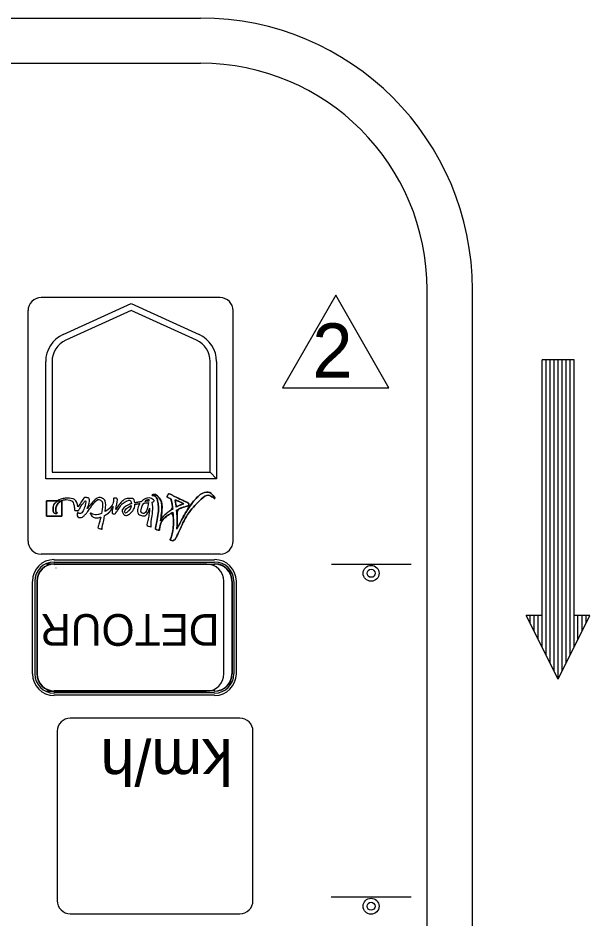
# Model space of a CAD drawing. Extents: x 1806 to 2022, y 110 to 389.
# Drawn here: x 1952.45 to 1967.73, y 255.29 to 279.36 of the extents above; entities that cross this region are included whole.
import ezdxf

# ---------------------------------------------------------------- set-up
doc = ezdxf.new("R2010")
doc.units = 0
for name, color, linetype in [('Level 10', 7, 'Continuous'), ('Level 2', 7, 'Continuous'), ('Level 44', 7, 'Continuous'), ('Level 50', 7, 'Continuous'), ('Level 53', 7, 'Continuous'), ('Level 60', 7, 'Continuous')]:
    doc.layers.add(name, color=color, linetype=linetype)

msp = doc.modelspace()

# ---------------------------------------------------------------- linework, layer by layer
at = {"layer": 'Level 10'}
for p, q in [((1895.86, 279.357), (1957.331, 279.357)), ((1895.86, 278.148), (1957.331, 278.148)), ((1963.38, 232.973), (1963.38, 272.1)), ((1964.59, 233.074), (1964.59, 272.1))]:
    msp.add_line(p, q, dxfattribs=at)
for radius in [7.258, 6.048]:
    msp.add_arc((1957.332, 272.1), radius, 0, 90, dxfattribs=at)
at = {"layer": 'Level 2'}
for p, q in [((1957.854, 271.887), (1953.069, 271.887)), ((1952.722, 265.385), (1952.722, 271.54)), ((1953.661, 270.905), (1955.476, 271.73)), ((1955.476, 271.542), (1953.732, 270.749)), ((1955.476, 271.73), (1957.29, 270.905)), ((1957.219, 270.749), (1955.476, 271.542)), ((1958.201, 265.385), (1958.201, 271.54)), ((1953.193, 267.05), (1953.193, 270.178)), ((1953.364, 270.178), (1953.364, 267.222)), ((1957.587, 267.222), (1957.587, 270.178)), ((1957.758, 270.178), (1957.758, 267.05)), ((1953.364, 267.222), (1957.587, 267.222)), ((1957.758, 267.05), (1957.587, 267.222)), ((1957.587, 267.222), (1957.758, 267.05)), ((1957.758, 267.05), (1953.193, 267.05)), ((1957.854, 265.038), (1953.069, 265.038)), ((1957.854, 265.038), (1953.069, 265.038))]:
    msp.add_line(p, q, dxfattribs=at)
for centre, radius, start, end in [((1953.069, 271.54), 0.347, 90, 180), ((1957.854, 271.54), 0.347, 360, 90), ((1953.992, 270.178), 0.799, 114.4568, 180), ((1956.959, 270.178), 0.799, 360, 65.5432), ((1953.992, 270.178), 0.628, 114.4568, 180), ((1956.959, 270.178), 0.628, 360, 65.5432), ((1953.069, 265.385), 0.347, 180, 270), ((1957.854, 265.385), 0.347, 270, 360)]:
    msp.add_arc(centre, radius, start, end, dxfattribs=at)
at = {"layer": 'Level 44'}
for p, q in [((1957.496, 264.768), (1953.205, 264.768)), ((1953.414, 264.887), (1957.705, 264.887)), ((1953.414, 264.822), (1957.705, 264.822)), ((1953.418, 264.77), (1953.414, 264.768)), ((1953.414, 264.768), (1957.705, 264.768)), ((1953.414, 264.768), (1957.705, 264.768)), ((1953.424, 264.77), (1957.715, 264.77)), ((1955.339, 264.774), (1955.339, 264.774)), ((1955.339, 264.774), (1955.339, 264.774)), ((1955.349, 264.776), (1955.349, 264.776)), ((1955.571, 264.774), (1955.571, 264.774)), ((1962.956, 264.762), (1960.823, 264.762)), ((1953.442, 264.722), (1953.438, 264.72)), ((1953.471, 264.664), (1953.467, 264.662)), ((1952.843, 261.84), (1952.843, 264.305)), ((1952.908, 261.84), (1952.908, 264.305)), ((1952.962, 261.84), (1952.962, 264.305)), ((1952.962, 261.84), (1952.962, 264.305)), ((1952.964, 264.305), (1952.964, 261.84)), ((1952.972, 261.842), (1952.972, 264.307)), ((1957.948, 261.84), (1957.948, 264.305)), ((1958.161, 264.305), (1958.161, 261.84)), ((1958.161, 264.305), (1958.161, 261.84)), ((1958.171, 264.307), (1958.171, 261.842)), ((1958.215, 264.305), (1958.215, 261.84)), ((1958.28, 264.305), (1958.28, 261.84)), ((1953.201, 261.378), (1957.492, 261.378)), ((1957.705, 261.384), (1953.414, 261.384)), ((1957.705, 261.384), (1953.414, 261.384)), ((1957.705, 261.33), (1953.414, 261.33)), ((1957.705, 261.265), (1953.414, 261.265)), ((1957.715, 261.386), (1953.424, 261.386)), ((1958.379, 260.654), (1953.851, 260.654)), ((1953.501, 260.306), (1953.501, 260.305)), ((1953.501, 260.305), (1953.501, 255.775)), ((1958.729, 255.775), (1958.729, 260.305)), ((1962.954, 255.867), (1960.821, 255.867)), ((1953.851, 255.426), (1958.379, 255.426))]:
    msp.add_line(p, q, dxfattribs=at)
for centre, radius in [((1961.885, 264.523), 0.213), ((1961.885, 264.523), 0.107), ((1961.883, 255.629), 0.213), ((1961.883, 255.629), 0.107)]:
    msp.add_circle(centre, radius, dxfattribs=at)
for centre, radius, start, end in [((1953.418, 264.309), 0.581, 90, 180), ((1953.418, 264.309), 0.516, 90, 180), ((1953.418, 264.309), 0.462, 90, 180), ((1953.418, 264.309), 0.462, 90, 180), ((1953.42, 264.309), 0.462, 90, 180), ((1953.428, 264.311), 0.462, 90, 180), ((1957.492, 264.309), 0.462, 0, 90), ((1957.705, 264.309), 0.581, 0, 90), ((1957.705, 264.309), 0.516, 0, 90), ((1957.705, 264.309), 0.462, 0, 90), ((1957.705, 264.309), 0.462, 0, 90), ((1957.715, 264.311), 0.462, 0, 90), ((1953.418, 261.839), 0.581, 180, 270), ((1953.418, 261.839), 0.516, 180, 270), ((1953.418, 261.839), 0.462, 180, 270), ((1953.418, 261.839), 0.462, 180, 270), ((1953.42, 261.839), 0.462, 180, 270), ((1953.428, 261.841), 0.462, 180, 270), ((1957.492, 261.839), 0.462, 270, 0), ((1957.705, 261.839), 0.462, 270, 360), ((1957.705, 261.839), 0.581, 270, 360), ((1957.705, 261.839), 0.516, 270, 360), ((1957.705, 261.839), 0.462, 270, 360), ((1957.715, 261.841), 0.462, 270, 360), ((1953.851, 260.306), 0.349, 90, 180), ((1958.38, 260.306), 0.349, 0, 90), ((1953.851, 255.777), 0.349, 180, 270), ((1958.38, 255.777), 0.349, 270, 0)]:
    msp.add_arc(centre, radius, start, end, dxfattribs=at)
at = {"layer": 'Level 50'}
for p, q in [((1966.45, 263.397), (1966.45, 270.224)), ((1967.304, 270.224), (1966.45, 270.224)), ((1966.45, 262.544), (1966.45, 270.224)), ((1966.557, 262.331), (1966.557, 270.224)), ((1966.664, 262.117), (1966.664, 270.224)), ((1966.77, 261.904), (1966.77, 270.224)), ((1966.877, 261.691), (1966.877, 270.224)), ((1966.984, 261.904), (1966.984, 270.224)), ((1967.09, 262.117), (1967.09, 270.224)), ((1967.197, 262.331), (1967.197, 270.224)), ((1967.304, 263.397), (1967.304, 270.224)), ((1967.304, 262.544), (1967.304, 270.224)), ((1966.877, 261.691), (1966.024, 263.397)), ((1966.45, 263.397), (1966.024, 263.397)), ((1966.13, 263.184), (1966.13, 263.397)), ((1966.237, 262.97), (1966.237, 263.397)), ((1966.344, 262.757), (1966.344, 263.397)), ((1966.877, 261.691), (1967.73, 263.397)), ((1967.73, 263.397), (1967.304, 263.397)), ((1967.41, 262.757), (1967.41, 263.397)), ((1967.517, 262.97), (1967.517, 263.397)), ((1967.624, 263.184), (1967.624, 263.397))]:
    msp.add_line(p, q, dxfattribs=at)
at = {"layer": 'Level 53'}
msp.add_line((1953.513, 266.455), (1953.613, 266.455), dxfattribs=at)
msp.add_lwpolyline([(1953.513, 266.455), (1953.218, 266.455), (1953.218, 266.048), (1953.625, 266.048), (1953.625, 266.455), (1953.613, 266.455)], dxfattribs=at)
for points, degree in [([(1956.067, 266.603), (1956.111, 266.596), (1956.168, 266.537), (1956.185, 266.439), (1956.217, 266.262), (1956.198, 266.088), (1956.146, 265.828), (1956.136, 265.779), (1956.103, 265.694), (1956.21, 265.678), (1956.243, 265.673), (1956.226, 265.689), (1956.235, 265.734), (1956.276, 265.928), (1956.434, 266.067), (1956.593, 266.16), (1956.61, 265.939), (1956.603, 265.693), (1956.561, 265.542), (1956.526, 265.415), (1956.484, 265.439), (1956.536, 265.412), (1956.591, 265.384), (1956.649, 265.421), (1956.697, 265.516), (1956.744, 265.61), (1956.963, 266.125), (1957.312, 266.472), (1957.491, 266.649), (1957.652, 266.558), (1957.684, 266.531), (1957.711, 266.508), (1957.72, 266.543), (1957.688, 266.578), (1957.543, 266.734), (1957.332, 266.644), (1957.255, 266.567), (1957.043, 266.355), (1956.796, 265.898), (1956.696, 265.704), (1956.706, 265.813), (1956.709, 265.997), (1956.688, 266.211), (1956.796, 266.264), (1956.893, 266.295), (1956.939, 266.307), (1956.988, 266.32), (1957.019, 266.34), (1957.02, 266.363), (1957.021, 266.388), (1956.988, 266.409), (1956.94, 266.432), (1956.854, 266.472), (1956.604, 266.591), (1956.542, 266.627), (1956.489, 266.658), (1956.463, 266.634), (1956.448, 266.6), (1956.427, 266.557), (1956.483, 266.532), (1956.538, 266.516), (1956.558, 266.443), (1956.575, 266.346), (1956.586, 266.238), (1956.459, 266.16), (1956.333, 266.055), (1956.261, 265.925), (1956.279, 266.034), (1956.326, 266.405), (1956.209, 266.561), (1956.183, 266.596), (1956.126, 266.634), (1956.071, 266.628), (1956.045, 266.625), (1956.031, 266.608), (1956.034, 266.603), (1956.037, 266.597), (1956.052, 266.605), (1956.067, 266.603)], 3), ([(1956.593, 266.16), (1956.61, 265.939), (1956.603, 265.693), (1956.561, 265.542), (1956.526, 265.415), (1956.484, 265.439), (1956.536, 265.412), (1956.591, 265.384), (1956.649, 265.421), (1956.697, 265.516), (1956.744, 265.61), (1956.963, 266.125), (1957.312, 266.472), (1957.491, 266.649), (1957.652, 266.558), (1957.684, 266.531), (1957.711, 266.508), (1957.72, 266.543), (1957.688, 266.578), (1957.543, 266.734), (1957.332, 266.644), (1957.255, 266.567), (1957.043, 266.355), (1956.796, 265.898), (1956.696, 265.704)], 3), ([(1953.625, 266.048), (1953.625, 266.048), (1953.625, 266.455), (1953.625, 266.455), (1953.625, 266.455), (1953.613, 266.455), (1953.613, 266.455), (1953.525, 266.402), (1953.465, 266.301), (1953.465, 266.218), (1953.466, 266.146), (1953.504, 266.149), (1953.499, 266.139), (1953.487, 266.11), (1953.397, 266.127), (1953.392, 266.228), (1953.387, 266.315), (1953.432, 266.398), (1953.513, 266.455), (1953.513, 266.455), (1953.218, 266.455), (1953.218, 266.455), (1953.218, 266.455), (1953.218, 266.048), (1953.218, 266.048), (1953.218, 266.048), (1953.625, 266.048), (1953.625, 266.048)], 3), ([(1953.613, 266.455), (1953.525, 266.402), (1953.465, 266.301), (1953.465, 266.218), (1953.466, 266.146), (1953.504, 266.149), (1953.499, 266.139), (1953.487, 266.11), (1953.397, 266.127), (1953.392, 266.228), (1953.387, 266.315), (1953.432, 266.398), (1953.513, 266.455)], 3), ([(1954.056, 266.3), (1954.046, 266.384), (1953.99, 266.529), (1953.764, 266.529), (1953.663, 266.529), (1953.577, 266.5), (1953.513, 266.455)], 3), ([(1953.613, 266.455), (1953.651, 266.477), (1953.693, 266.491), (1953.739, 266.491)], 2), ([(1953.739, 266.491), (1953.906, 266.491), (1953.949, 266.361), (1953.958, 266.297), (1953.963, 266.254), (1953.954, 266.192), (1954.028, 266.2), (1954.079, 266.206), (1954.126, 266.307), (1954.192, 266.392), (1954.248, 266.464), (1954.273, 266.458), (1954.26, 266.395), (1954.244, 266.317), (1954.178, 266.133), (1954.104, 266.12), (1954.069, 266.114), (1954.057, 266.174), (1954.041, 266.136), (1954.025, 266.098), (1954.039, 266.016), (1954.117, 266.016), (1954.171, 266.016), (1954.236, 266.074), (1954.289, 266.139), (1954.336, 266.196), (1954.57, 266.541), (1954.669, 266.467), (1954.715, 266.432), (1954.711, 266.29), (1954.682, 266.123)], 3), ([(1954.303, 266.251), (1954.355, 266.369), (1954.385, 266.52), (1954.306, 266.543), (1954.214, 266.57), (1954.141, 266.417), (1954.056, 266.3)], 3), ([(1954.784, 266.175), (1954.802, 266.333), (1954.796, 266.474), (1954.724, 266.519), (1954.592, 266.601), (1954.405, 266.384), (1954.303, 266.251)], 3), ([(1955.069, 266.227), (1955.079, 266.325), (1955.142, 266.539), (1955.034, 266.528), (1954.991, 266.524), (1955.009, 266.517), (1955.007, 266.48), (1954.997, 266.351), (1954.89, 266.242), (1954.784, 266.175)], 3), ([(1954.994, 266.307), (1954.984, 266.257), (1954.968, 266.201), (1954.967, 266.163), (1954.966, 266.124), (1954.993, 266.115), (1955.003, 266.112), (1955.026, 266.105), (1955.054, 266.117), (1955.082, 266.155), (1955.146, 266.246), (1955.228, 266.39), (1955.352, 266.45), (1955.441, 266.494), (1955.48, 266.45), (1955.482, 266.383)], 3), ([(1955.577, 266.406), (1955.568, 266.478), (1955.522, 266.533), (1955.413, 266.523), (1955.258, 266.508), (1955.121, 266.318), (1955.069, 266.227)], 3), ([(1956.038, 266.422), (1956.084, 266.437), (1956.103, 266.471), (1956.044, 266.508), (1956.003, 266.533), (1955.914, 266.541), (1955.823, 266.497), (1955.791, 266.481), (1955.763, 266.458), (1955.739, 266.432)], 3), ([(1955.844, 266.444), (1955.866, 266.468), (1955.891, 266.485), (1955.918, 266.489)], 2), ([(1955.945, 266.451), (1955.922, 266.45), (1955.886, 266.448), (1955.844, 266.444)], 2), ([(1955.918, 266.489), (1955.933, 266.492), (1955.945, 266.492), (1955.955, 266.49)], 2), ([(1955.955, 266.49), (1955.949, 266.485), (1955.946, 266.477), (1955.946, 266.469), (1955.946, 266.463), (1955.945, 266.457), (1955.945, 266.451)], 3), ([(1956.261, 265.925), (1956.279, 266.034), (1956.326, 266.405), (1956.209, 266.561), (1956.183, 266.596), (1956.126, 266.634), (1956.071, 266.628), (1956.045, 266.625), (1956.031, 266.608), (1956.034, 266.603), (1956.037, 266.597), (1956.052, 266.605), (1956.067, 266.603)], 3), ([(1956.067, 266.603), (1956.111, 266.596), (1956.168, 266.537), (1956.185, 266.439), (1956.217, 266.262), (1956.198, 266.088), (1956.146, 265.828), (1956.136, 265.779), (1956.103, 265.694), (1956.21, 265.678), (1956.243, 265.673), (1956.226, 265.689), (1956.235, 265.734), (1956.276, 265.928), (1956.434, 266.067), (1956.593, 266.16)], 3), ([(1956.688, 266.211), (1956.796, 266.264), (1956.893, 266.295), (1956.939, 266.307), (1956.988, 266.32), (1957.019, 266.34), (1957.02, 266.363), (1957.021, 266.388), (1956.988, 266.409), (1956.94, 266.432), (1956.854, 266.472), (1956.604, 266.591), (1956.542, 266.627), (1956.489, 266.658), (1956.463, 266.634), (1956.448, 266.6), (1956.427, 266.557), (1956.483, 266.532), (1956.538, 266.516)], 3), ([(1956.538, 266.516), (1956.558, 266.443), (1956.575, 266.346), (1956.586, 266.238)], 2), ([(1956.68, 266.291), (1956.67, 266.377), (1956.658, 266.44), (1956.646, 266.486)], 2), ([(1956.646, 266.486), (1956.702, 266.466), (1956.781, 266.434), (1956.884, 266.381)], 2), ([(1956.884, 266.381), (1956.827, 266.361), (1956.755, 266.331), (1956.68, 266.291), (1956.67, 266.377), (1956.658, 266.44), (1956.646, 266.486), (1956.702, 266.466), (1956.781, 266.434), (1956.884, 266.381)], 3), ([(1954.768, 266.065), (1954.854, 266.115), (1954.935, 266.198), (1954.994, 266.307)], 2), ([(1955.482, 266.383), (1955.465, 266.378), (1955.449, 266.372), (1955.436, 266.366), (1955.275, 266.295), (1955.219, 266.187), (1955.26, 266.121), (1955.299, 266.059), (1955.41, 266.078), (1955.498, 266.17), (1955.541, 266.216), (1955.575, 266.294), (1955.578, 266.366)], 3), ([(1955.396, 266.179), (1955.342, 266.129), (1955.315, 266.132), (1955.308, 266.146), (1955.293, 266.175), (1955.356, 266.277), (1955.478, 266.334)], 3), ([(1955.478, 266.334), (1955.468, 266.278), (1955.439, 266.218), (1955.396, 266.179)], 2), ([(1955.739, 266.432), (1955.685, 266.425), (1955.629, 266.416), (1955.577, 266.406)], 2), ([(1955.578, 266.366), (1955.616, 266.374), (1955.658, 266.381), (1955.706, 266.387)], 2), ([(1955.706, 266.387), (1955.631, 266.264), (1955.637, 266.098), (1955.748, 266.07), (1955.876, 266.038), (1955.941, 266.163), (1955.969, 266.266)], 3), ([(1955.941, 266.411), (1955.924, 266.28), (1955.856, 266.098), (1955.771, 266.128), (1955.723, 266.144), (1955.748, 266.298), (1955.811, 266.399)], 3), ([(1955.811, 266.399), (1955.852, 266.404), (1955.895, 266.407), (1955.941, 266.411)], 2), ([(1955.969, 266.266), (1955.96, 266.163), (1955.944, 266.036), (1955.92, 265.919), (1955.911, 265.87), (1955.877, 265.785), (1955.984, 265.768), (1956.017, 265.763), (1956.012, 265.779), (1956.009, 265.825), (1956.006, 265.886), (1956.074, 266.259), (1956.038, 266.422)], 3), ([(1956.586, 266.238), (1956.459, 266.16), (1956.333, 266.055), (1956.261, 265.925)], 2), ([(1956.884, 266.381), (1956.827, 266.361), (1956.755, 266.331), (1956.68, 266.291)], 2), ([(1956.696, 265.704), (1956.706, 265.813), (1956.709, 265.997), (1956.688, 266.211)], 2), ([(1954.682, 266.123), (1954.565, 266.078), (1954.468, 266.092), (1954.413, 266.119), (1954.386, 266.132), (1954.382, 266.13), (1954.394, 266.1), (1954.411, 266.056), (1954.505, 265.988), (1954.652, 266.019), (1954.655, 266.02), (1954.659, 266.021), (1954.662, 266.022)], 3), ([(1954.662, 266.022), (1954.65, 265.967), (1954.637, 265.912), (1954.622, 265.858), (1954.608, 265.809), (1954.568, 265.724), (1954.673, 265.708), (1954.706, 265.703), (1954.692, 265.719), (1954.703, 265.764), (1954.724, 265.848), (1954.749, 265.956), (1954.768, 266.065)], 3)]:
    msp.add_open_spline(points, degree=degree, dxfattribs=at)
at = {"layer": 'Level 60'}
for points in [[(1960.94, 271.952), (1959.547, 269.527)], [(1962.334, 269.527), (1960.94, 271.952)], [(1959.547, 269.527), (1959.521, 269.482), (1962.36, 269.482), (1962.334, 269.527)]]:
    msp.add_lwpolyline(points, dxfattribs=at)

# ---------------------------------------------------------------- texts
at = {"layer": 'Level 44'}
for s, height, p in [('DETOUR', 0.8479, (1957.834, 263.434)), ('km/h', 1.218, (1958.187, 260.096)), ('km/h', 1.218, (1958.187, 260.096))]:
    msp.add_text(s, height=height, rotation=180, dxfattribs=at).set_placement(p)
at = {"layer": 'Level 60'}
msp.add_text('2', height=1.448, rotation=360, dxfattribs=at).set_placement((1960.313, 269.751))

doc.saveas('drawing.dxf')
